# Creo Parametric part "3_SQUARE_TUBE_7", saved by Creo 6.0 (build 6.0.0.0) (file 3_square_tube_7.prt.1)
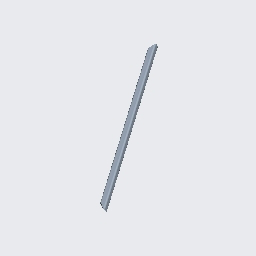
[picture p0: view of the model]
Units: Custom; MM, KILOGRAM, SECS
Materials in the file: STEEL

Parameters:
  BUW_NAME = "SQUARE TUBE"
  BUW_TYPE = "DIN EN 10219"
  BUW_SIZE = "25x25x3.0"
  BUW_LENGTH_STR = "705"
  PTC_MATERIAL_NAME = "STEEL"
  BUW_PROFIL_TYPE = "square_tube"
  BUW_PROFILE_PATH = "parts//profiles/steel_beams_mm/"
  BUW_PROFILE_NAME_LANG = "SQUARE TUBE"
  BUW_TAB_SEL_INFO = "-2 TYPE DIN_EN_10219-1997 SIZE_DINEN_10219 25x25x3.0"
  NAMING = "SQUARE TUBE"
  DESIGNATION = "DIN EN 10219 25x25x3.0 x 705"
  PROFIL_RASTER_POS = "X_0"
  BUW_OBJECT_ROLE = "PROFIL_SYSTEM_BORE_END_POINTS"
  PRO_UNIT_SYS = "Custom"

Other parameters: BUW_LENGTH, LENGTH, BUW_LENGTH_Z_MIN_PARAM, D8, D93, D94, d26, d8, d93, d94, d98, D98, SHEAR_MODULUS, THERM_EXPANSION_REF_TEMPERATURE, STRUCTURAL_DAMPING_COEFFICIENT, STRESS_LIMIT_FOR_TENSION, STRESS_LIMIT_FOR_COMPRESSION, STRESS_LIMIT_FOR_SHEAR, EMISSIVITY

Created from: SQUARE_TUBE.PRT

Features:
  1. datum plane "YZ"
  2. datum plane "XZ"
  3. datum plane "XY"
  4. coordinate system
  5. coordinate system
  6. coordinate system
  7. coordinate system
  8. datum plane "DTM3"
  9. datum plane "DTM4"
  10. datum plane "DTM5"
  11. protrusion
  12. round
  13. round
  14. datum axis
  15. datum point "PNT0"
  16. datum point

Other named items: PROFIL_CUT_QUILT, PROFILE_LENGTH_DIM, CONTACT_SURF_3, CONTACT_SURF_2, CONTACT_SURF_1, CONTACT_SURF_0, E, START_SURFACE, END_SURFACE, SIDE_SURF_3, SIDE_SURF_0, SIDE_SURF_1, SIDE_SURF_2, EDGE_7_S, EDGE_7_E, EDGE_1_S, EDGE_1_E, EDGE_3_S, EDGE_3_E, EDGE_5_S, EDGE_5_E, EDGE_6_S, EDGE_4_S, EDGE_2_S, EDGE_0_S, EDGE_6_E, EDGE_4_E, EDGE_2_E, EDGE_0_E, CS0, CS_S, CS_E, CS3

Named dimensions: X_ROT_S, Y_ROT_S, Z_OFF_S, X_ROT_E, Y_ROT_E, Z_OFF_E, PC_L, BUW_LENGTH_Z_MIN, BUW_LENGTH_DIM

Layers: 00_PROFIL_DATUM, 00_PROFIL_DRW_HIDE, 00_PROFIL_END_CSYS, 00_PROFIL_GEOMETRY, 00_PROFIL_QUILT, 00_PROFIL_SIZE_NOTE

Surfaces: 16 plane, 12 cylinder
